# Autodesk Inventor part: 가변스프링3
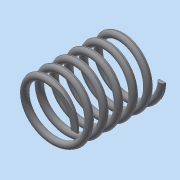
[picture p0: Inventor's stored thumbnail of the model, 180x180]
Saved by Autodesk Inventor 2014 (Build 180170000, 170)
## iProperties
Created: 2023-01
Part Number: 가변스프링3
Material: 일반
Document SubType Name: Modeling
Designer: dg
Density: 1 g/cm^3
Appearance: 기본값
Mass: 0.990077 g
Surface Area: 20.0872 cm^2
Volume: 0.990077 cm^3
Author: dg
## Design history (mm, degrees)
sketch "스케치1"
  geometry: L1 (8.5, 0)-(0, 0); L2 (0, 0)-(0, 26.33); L3 (0, 26.33)-(8.5, 26.33); C1 r 1 at (8.5, 0)
  constraints: 6 end point, 1 centre point, 1 coincident, 1 horizontal, 1 parallel, 1 vertical, 1 vertical alignment
  dimensions: "d0" = 2 diameter of C1; "d1" = 26.33013 distance of L1.end L2.end (derived); "d2" = 17 diameter of L1.start L2
feature "코일1" sketch "스케치1" pitch "d3" = 10; turns "d5" = 6; dims "d4" = 26.33013 (= d1), "d6" = 0, angle "d7" = 90 deg, angle "d8" = 90 deg, "d9" = 0, "d10" = 0
node "작업 평면1"
node "작업 평면2"
feature "분할1"
feature "분할2"
node "솔리드1"
other parameters: "d11" = 90 deg, "d12" = 90 deg
